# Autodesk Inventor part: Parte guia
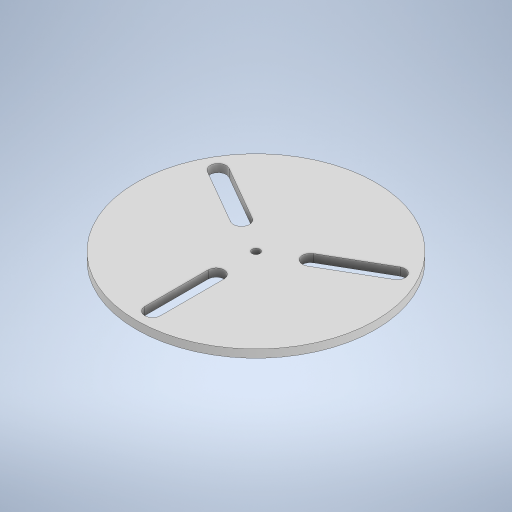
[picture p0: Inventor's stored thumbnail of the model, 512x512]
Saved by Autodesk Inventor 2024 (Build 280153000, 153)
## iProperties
Created: 2024-05
Part Number: Parte guia
Material: Generic
Document SubType Name: Modeling
Designer: dylan
Density: 1 g/cm^3
Appearance: Default
Author: dylan
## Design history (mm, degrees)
sketch "Sketch1"
  geometry: C1 r 75.15 at (0, 0); 1 further point
  constraints: 1 centre point, 1 coincident
  dimensions: "d0" = 150.3 diameter of C1
extrude "Extrusion1" new body sketch "Sketch1" distance "d1" = 5; taper "d2" = 0 deg
sketch "Sketch2"
  geometry: L1 (0, 0)-(0, -25); L2 (0, -25)-(0, -65); L3 (0, -65)-(0, -25); L4 (5, -65)-(5, -25); L5 (-5, -25)-(-5, -65); L6 (53.792, 36.83)-(19.151, 16.83); L7 (24.151, 8.17)-(58.792, 28.17); L8 (-58.792, 28.17)-(-24.151, 8.17); L9 (-19.151, 16.83)-(-53.792, 36.83); C1 r 75.15 at (0, 0) reference; A1 r 5 centre (0, -65) between (-5, -65) and (5, -65); A2 r 5 centre (0, -25) between (5, -25) and (-5, -25); A3 r 5 centre (21.651, 12.5) between (19.151, 16.83) and (24.151, 8.17); A4 r 5 centre (56.292, 32.5) between (58.792, 28.17) and (53.792, 36.83); A5 r 5 centre (-21.651, 12.5) between (-24.151, 8.17) and (-19.151, 16.83); A6 r 5 centre (-56.292, 32.5) between (-53.792, 36.83) and (-58.792, 28.17); 2 further points
  constraints: 20 end point, 12 point on circle, 6 centre point, 4 tangent, 2 equal length, 2 midpoint, 2 vertical, 31 other
  dimensions: "d3" = 25 distance of L1.start L1.end; "d6" = 40 distance of L1.end L2.end; "d7" = 10 diameter of A2; "d16" = 360 deg dimension on L1.start L4.start (derived)
extrude "Extrusion2" cut sketch "Sketch2" distance "d12" = 5; taper "d13" = 0 deg
sketch "Sketch3"
  geometry: C1 r 2.5 at (0, 0); 1 further point
  constraints: 1 centre point, 1 coincident
  dimensions: "d18" = 5 diameter of C1
extrude "Extrusion3" cut sketch "Sketch3" distance "d19" = 5; taper "d20" = 0 deg
body "Solid1"
